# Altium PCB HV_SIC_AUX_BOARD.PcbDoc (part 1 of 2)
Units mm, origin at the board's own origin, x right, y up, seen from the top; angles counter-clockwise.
Board outline 121.92 x 53.34 mm, 4 copper layers (TOP, GND02, PWR03, BOTTOM), stack 1.6 mm thick; 125 components, 51 nets, 259 pads, 380 vias.
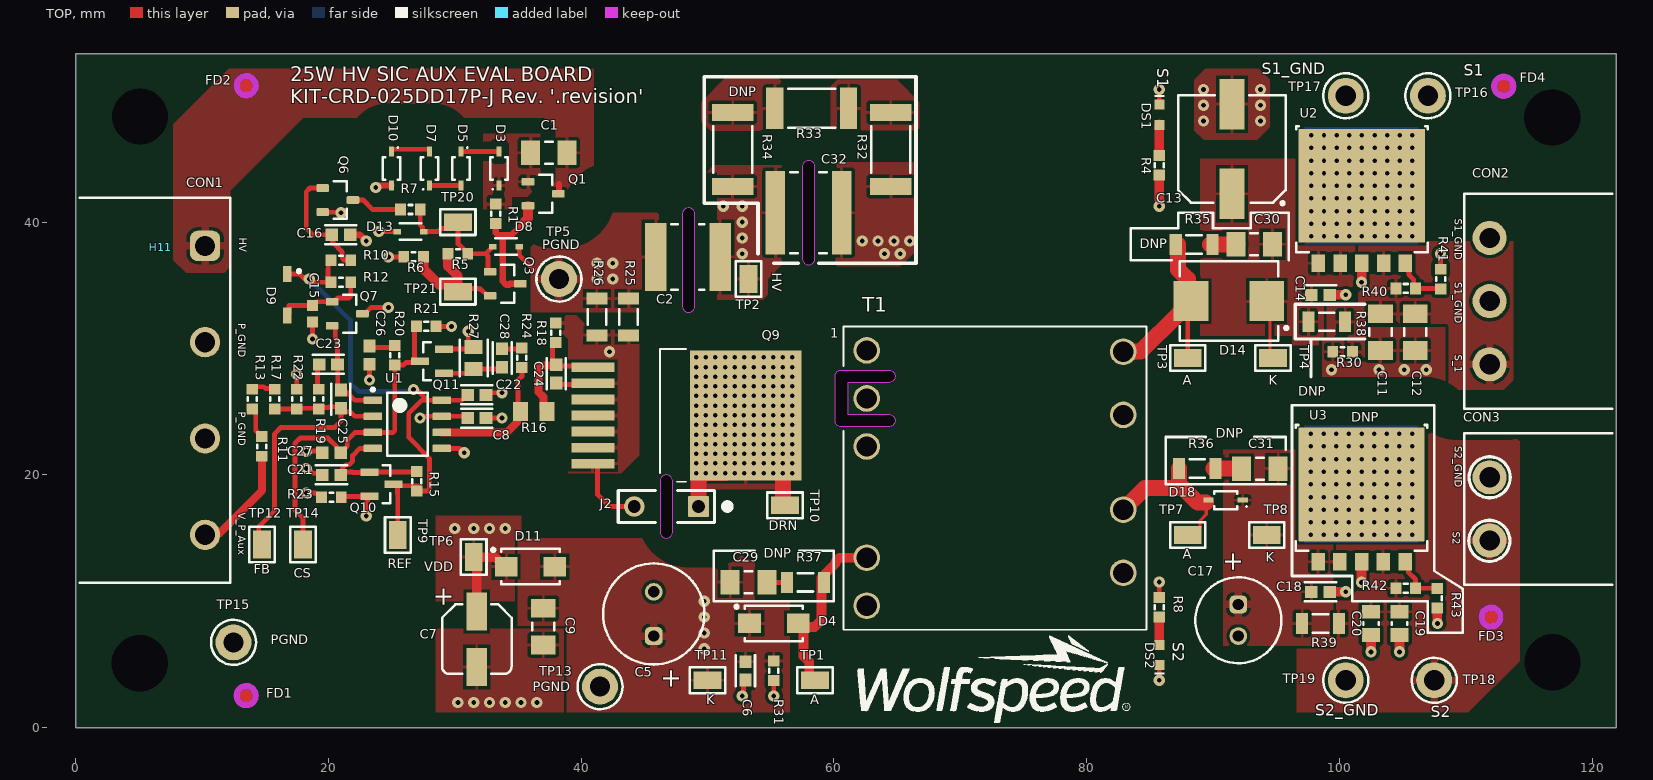
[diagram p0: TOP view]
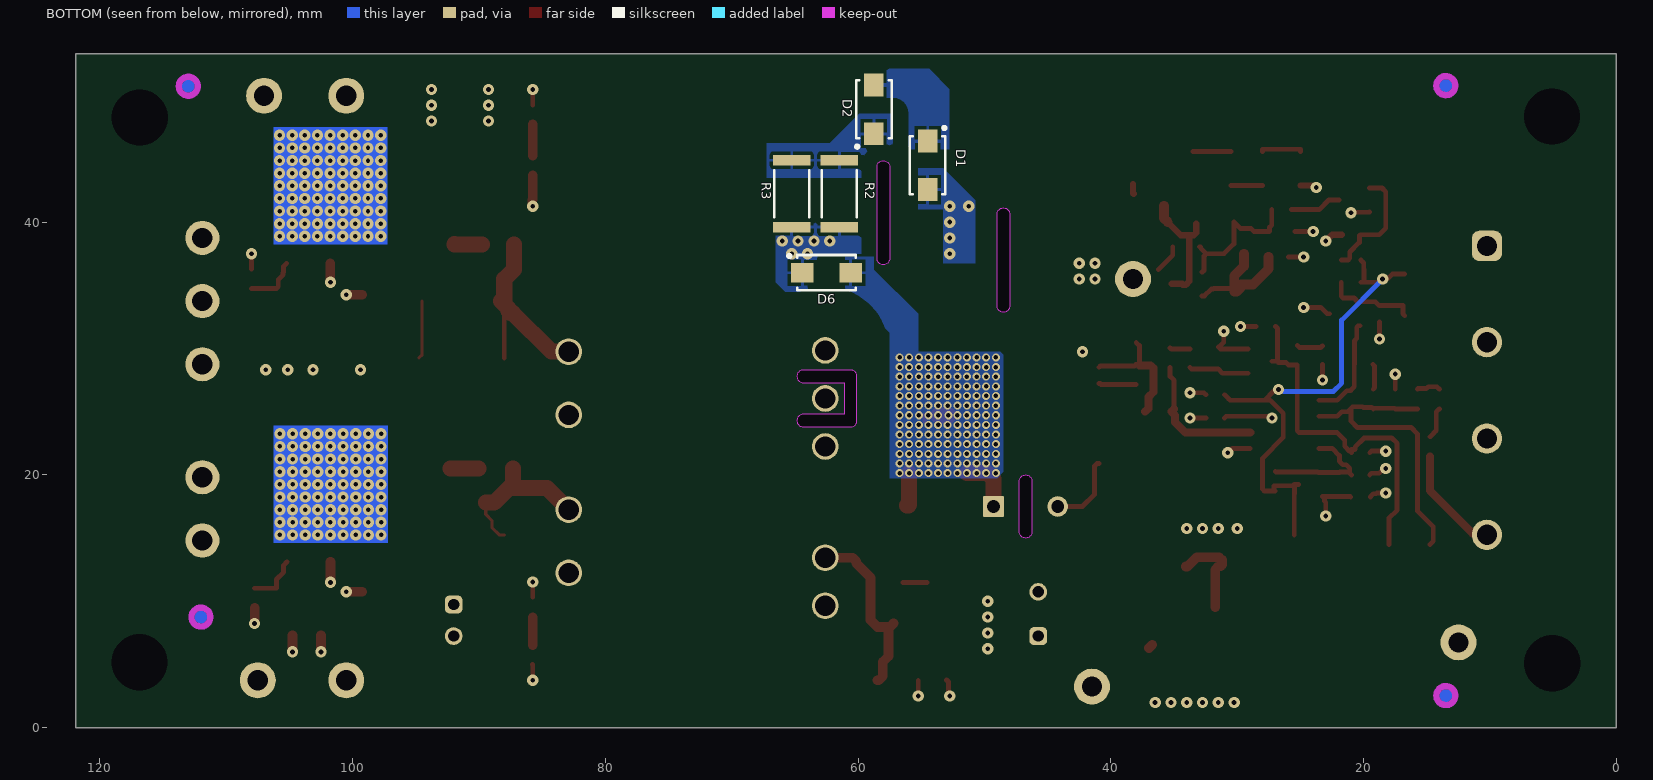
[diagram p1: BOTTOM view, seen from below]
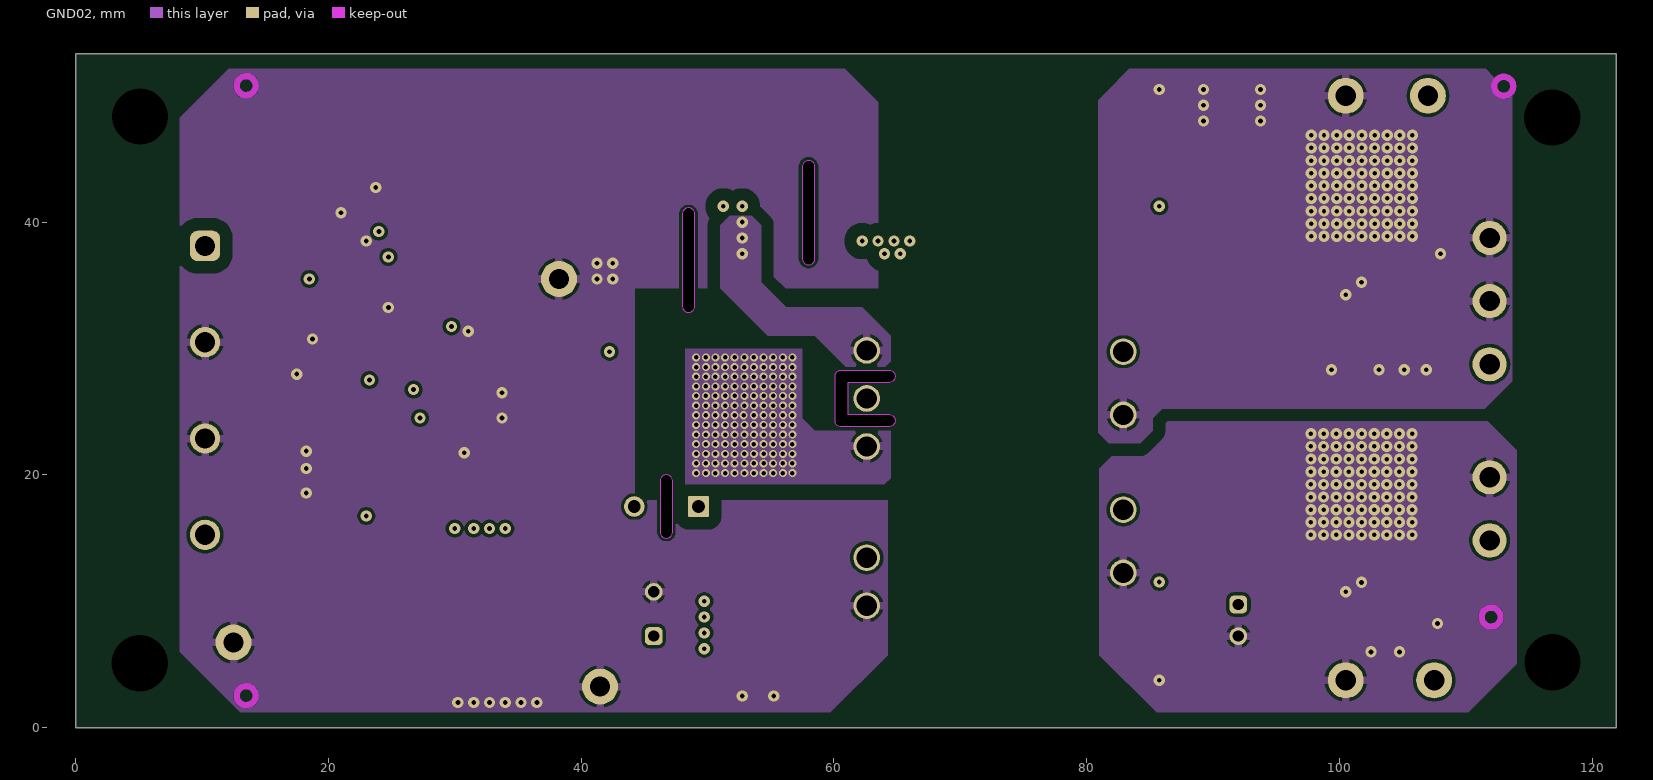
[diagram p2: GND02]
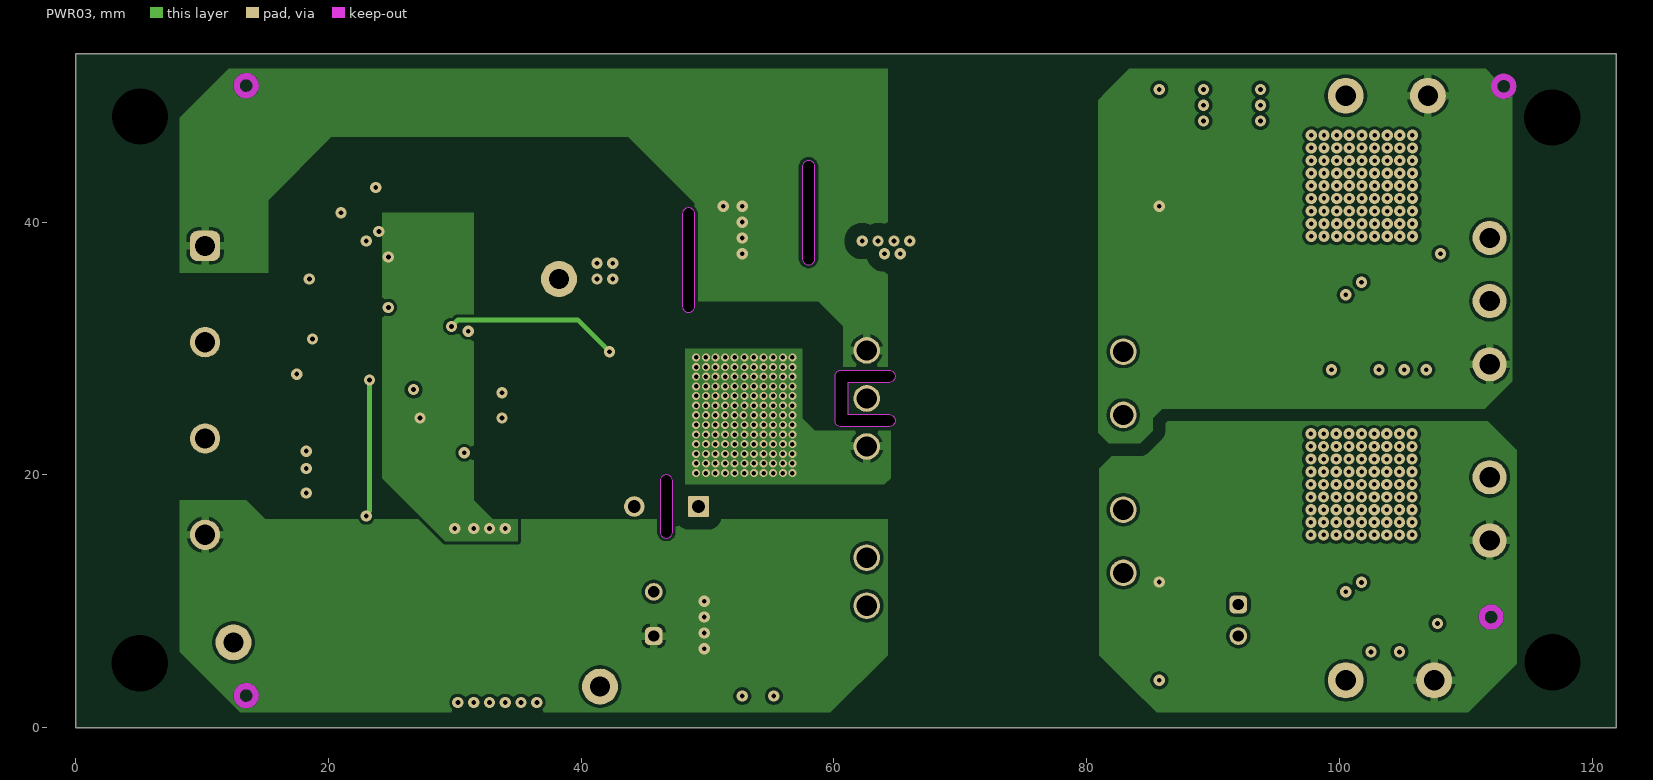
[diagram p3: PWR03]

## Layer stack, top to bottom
Top Solder: solder mask 0.0102, Solder Resist, Dk 3.5
TOP: signal copper 0.0356
Dielectric 1: prepreg 0.2159, FR-4, Dk 4.5
GND02: signal copper 0.0305
Dielectric2: core 1.0363, FR-4, Dk 4.5
PWR03: signal copper 0.0305
Dielectric3: prepreg 0.2159, FR-4, Dk 4.5
BOTTOM: signal copper 0.0356
Bottom Solder: solder mask 0.0102, Solder Resist, Dk 3.5

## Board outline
0,0 0,53.34 121.92,53.34 121.92,0
cut-out: 46.249,15.5 ccw(c46.75,15.5) 47.25,15.5 47.25,19.5 ccw(c46.75,19.5) 46.249,19.5
cut-out: 57.499,37.125 ccw(c58,37.125) 58.5,37.125 58.5,44.375 ccw(c58,44.375) 57.499,44.375
cut-out: 48,33.375 ccw(c48.5,33.375) 49.001,33.375 49.001,40.625 ccw(c48.5,40.625) 48,40.625

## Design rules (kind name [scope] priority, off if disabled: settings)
BoardOutlineClearance "BoardOutlineClearance Outer" [All] p1: gap=0.254 ignorepadtopadclearanceinfootprint=FALSE except(0: Arc-SplitContinuation Track-SplitContinuation SMDPad-SplitContinuation THPad-SplitContinuation Via-SplitContinuation Fill-SplitContinuation Poly-SplitContinuation Region-SplitContinuation Text-SplitContinuation; 1.2: Poly-OutlineEdge)
Clearance "Clearance Keepout" [IsKeepOut] p1: gap=0 ignorepadtopadclearanceinfootprint=FALSE
Clearance HV_INT [InNetClass('HV') and OnMid vs InNetClass('ISO') or InNetClass('P15') or InNetClass('Sec') or InNetClass('SW')] p2: gap=1 ignorepadtopadclearanceinfootprint=TRUE
Clearance SW_INT [InNetClass('SW')AND OnMid vs InNetClass('Sec')or InNetClass('ISO')or InNetClass('HV')  or InNetClass('P15')] p3: gap=1 ignorepadtopadclearanceinfootprint=FALSE
Clearance P15_INT [InNetClass('P15')AND OnMid vs InNetClass('Sec')or InNetClass('ISO')or InNetClass('HV')  or InNetClass('SW')] p4: gap=1 ignorepadtopadclearanceinfootprint=FALSE
Clearance SEC_INT [InNetClass('Sec')AND OnMid vs InNetClass('HV') or InNetClass('ISO') or InNetClass('P15') or InNetClass('SW')] p5: gap=1 ignorepadtopadclearanceinfootprint=FALSE
Clearance ISO_INT [InNetClass('ISO') and OnMid vs InNetClass('HV') or InNetClass('P15') or InNetClass('Sec') or InNetClass('SW')] p6: gap=1 ignorepadtopadclearanceinfootprint=FALSE
Clearance HV_EXT [InNetClass('HV') and (OnOutside or OnMultiLayer) vs InNetClass('ISO') or InNetClass('P15') or InNetClass('Sec') or InNetClass('SW')] p7: gap=4.01 ignorepadtopadclearanceinfootprint=FALSE
Clearance SW_EXT [InNetClass('SW')AND (OnOutside or OnMultiLayer) vs InNetClass('Sec')or InNetClass('ISO')or InNetClass('HV') or InNetClass('P15')] p8: gap=4.01 ignorepadtopadclearanceinfootprint=FALSE
Clearance P15_EXT [InNetClass('P15')AND (OnOutside or OnMultiLayer) vs InNetClass('Sec')or InNetClass('ISO')or InNetClass('HV') or InNetClass('SW')] p9: gap=4.01 ignorepadtopadclearanceinfootprint=FALSE
Clearance SEC_EXT [InNetClass('Sec')AND (OnOutside or OnMultiLayer) vs InNetClass('HV') or InNetClass('ISO') or InNetClass('P15')or InNetClass('SW')] p10: gap=4.01 ignorepadtopadclearanceinfootprint=FALSE
Clearance ISO_Ext [InNetClass('ISO') and (OnOutside or OnMultiLayer) vs InNetClass('HV') or InNetClass('P15') or InNetClass('Sec') or InNetClass('SW')] p11: gap=4.01 ignorepadtopadclearanceinfootprint=FALSE
Clearance "HV - ZV520 (260V)" [InNetClass('ZV520') vs InNetClass('HV')] p12: gap=1.25 ignorepadtopadclearanceinfootprint=FALSE
Clearance "HV - ZV260 (540V)" [InNetClass('V260') vs InNetClass('HV')] p13: gap=2.7 ignorepadtopadclearanceinfootprint=FALSE
Clearance "HV - ZV130 (670V)" [InNetClass('ZV130') vs InNetClass('HV')] p14: gap=3.4 ignorepadtopadclearanceinfootprint=FALSE
Clearance "ZV520 - ZV390 (130V)" [InNetClass('ZV520') vs InNetClass('ZV390')] p15: gap=0.6 ignorepadtopadclearanceinfootprint=FALSE
Clearance "ZV520 - ZV260 (260V)" [InNetClass('ZV520') vs InNetClass('ZV260')] p16: gap=1.25 ignorepadtopadclearanceinfootprint=FALSE
Clearance "ZV520 - ZV130 (390V)" [InNetClass('ZV520') vs InNetClass('ZV260')] p17: gap=2.5 ignorepadtopadclearanceinfootprint=FALSE
Clearance "ZV390 - ZV130 (260V)" [InNetClass('ZV390') vs InNetClass('ZV130')] p18: gap=1.25 ignorepadtopadclearanceinfootprint=FALSE
Clearance "ZV390 - ZV260 (130V)" [InNetClass('ZV390') vs InNetClass('ZV260')] p19: gap=0.6 ignorepadtopadclearanceinfootprint=FALSE
Clearance "ZV260 - ZV130 (130V)" [InNetClass('ZV390') vs InNetClass('ZV260')] p20: gap=0.6 ignorepadtopadclearanceinfootprint=FALSE
Clearance "Snubber Resistors" [InNetClass('V520') or InNetClass('V260')] p21: gap=2.5 ignorepadtopadclearanceinfootprint=FALSE
Clearance "TVS Diodes" [InNetClass('TVS_300V') or InNetClass('TVS_600V')] p22: gap=1.25 ignorepadtopadclearanceinfootprint=FALSE
Clearance "Clearance Default" [All] p23: gap=0.254 ignorepadtopadclearanceinfootprint=FALSE
ComponentClearance [All] p1 off: gap=0.001 collisioncheckmode=3 verticalgap=1.27 showdistances=FALSE
Creepage "Creepage HV" [InNetClass('HV') vs InNetClass('ISO') or InNetClass('P15') or InNetClass('Sec') or InNetClass('SW')] p1: checkdistance=4
Creepage "Creepage SW" [InNetClass('SW') vs InNetClass('ISO') or InNetClass('P15') or InNetClass('Sec') or InNetClass('HV')] p2: checkdistance=4
Creepage "Creepage P15" [InNetClass('P15') vs InNetClass('ISO') or InNetClass('SW') or InNetClass('Sec') or InNetClass('HV')] p3: checkdistance=4
Creepage "Creepage SEC" [InNetClass('Sec') vs InNetClass('ISO') or InNetClass('SW') or InNetClass('P15') or InNetClass('HV')] p4: checkdistance=4
Creepage "Creepage ISO" [InNetClass('ISO') vs InNetClass('Sec') or InNetClass('SW') or InNetClass('P15') or InNetClass('HV')] p5: checkdistance=4
HoleSize [All] p1: absolutevalues=TRUE maxlimit=5.08 minlimit=0.025 maxpercent=80.000 minpercent=20.000
MinimumSolderMaskSliver [All] p1: minsoldermaskwidth=0.102
PlaneConnect [All] p1: planeconnectstyle=Direct reliefexpansion=0.508 reliefentries=4 reliefconductorwidth=0.254 reliefairgap=0.254
PolygonConnect [All] p1: thpad.connectstyle=Relief thpad.reliefconductorwidth=0.635 thpad.reliefentries=4 thpad.polygonreliefangle="90 Angle" thpad.airgapwidth=0.254 smdpad.connectstyle=Relief smdpad.reliefconductorwidth=0.254 smdpad.reliefentries=4 smdpad.polygonreliefangle="90 Angle" smdpad.airgapwidth=0.254 via.connectstyle=Direct via.reliefconductorwidth=0.254 via.reliefentries=4 via.polygonreliefangle="90 Angle" via.airgapwidth=0.254
RoutingVias [All] p1: holewidth=0.711 width=1.27 viastyle="Through Hole" minholewidth=0.381 minwidth=0.889 maxholewidth=0.711 maxwidth=1.27
SilkToSilkClearance [All] p1: silktosilkclearance=0.127
SilkToSolderMaskClearance [IsPad] p1: minsilkscreentomaskgap=0.051 clearancetoexposedcopper=TRUE
SolderMaskExpansion [All] p1: expansion=0.102 istentingtop=FALSE
SupplyNets "Schematic Supply Nets_10" [InNet('S_1')] p1: voltage=0.000
SupplyNets "Schematic Supply Nets_9" [InNet('S1_GND')] p2: voltage=0.000
SupplyNets "Schematic Supply Nets_8" [InNet('S2_GND')] p3: voltage=0.000
SupplyNets "Schematic Supply Nets_7" [InNet('V_P_aux')] p4: voltage=0.000
SupplyNets "Schematic Supply Nets_6" [InNet('S_2')] p5: voltage=0.000
SupplyNets "Schematic Supply Nets" [InNet('PGND')] p6: voltage=0.000
Width [All] p1: maxlimit=1.27 minlimit=0.254 preferedwidth=0.381
24 further rules are at their usual default settings.

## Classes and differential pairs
net class ZV520: NetC1_2 NetQ1_2
net class ZV260: NetD5_2
net class TVS_600V: NetD2_1
net class TVS_300V: NetD1_1
net class V520: NetR33_1
net class V260: NetR32_1
net class ZV390: NetD3_2
net class SW: NetC32_2 NetD6_2
net class ZV130: NetD7_2
net class Sec: NetC13_1 NetC30_2 NetD14_2 NetDS1_2 NetR40_2 S1_GND S_1
net class P15: COMP CS FB NETC15_1 NETC16_2 NETC23_1 NETC24_2 NETC26_1 NETC26_2 NETC28_1 NETC28_2 NetC29_2 NetD4_2 NetD8_1 NetQ3_2 NETQ6_3 NetR11_1 NETR13_1 NETR16_1 PGND RT/CT SRC V_P_aux VDD VREF
net class ISO: NETC17_1 NetC31_2 NetD18_2 NetDS2_2 NetR42_2 S2_GND S_2
net class HV: HV_IN

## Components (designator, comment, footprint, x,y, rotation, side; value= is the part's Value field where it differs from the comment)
C1 "1206Y1K01P50DAR" CAPC3316X19N#1 37.45,45.5 r180 top value=1.5pF
C2 "C2220C164KFRLCTU" WS_C2220_B_Stacked 48.45,37.25 r180 top value=160nF
C5 "870235574001" 870235574001-Footprint-1 45.75,9 r270 top value=180µF
C6 "C1608X7R1V105K080AE" FP-C0603C-CF-IPC_B#1 53.007,4.5 r270 top value=1µF
C7 "875575659001" 875575659001-Footprint-1 31.75,7 r90 top value=22µF
C8 "C1608X7R1V105K080AE" FP-C0603C-CF-IPC_B#1 31.75,24.5 r0 top value=1µF
C9 "UMK316AB7475KL-T" CAPC3316X19N#1 37,8 r270 top value=4.7µF
C11 "CL31B106KAHNFNE" CAPC3316X19N#1 103.25,31.3 r270 top value=10µF
C12 "CL31B106KAHNFNE" CAPC3316X19N#1 106,31.3 r270 top value=10µF
C13 "EEE-FP1V221AP" FP-FPF-MFG 91.5,45.79 r270 top value=220µF
C14 "06035C105KAT2A" FP-C0603C-CF-IPC_B#2 98.5,34.25 r0 top value=1µF
C15 "CC0603KRX7R8BB334" WFP_C0603_C 18.75,32.75 r270 top value=330nF
C16 "CGA3E2X7R1H223K080AA" FP-C0603C-CF-IPC_B#1 21,39 r180 top value=22nF
C17 "870235373002" WCAP-PT5H_D6.3H11 92,8.5 r90 top value=180µF
C18 "C1608X7R1V105K080AE" FP-C0603C-CF-IPC_B#1 98.5,10.75 r0 top value=1µF
C19 "CC0805MKX7R7BB106" CAPC2012X15N 104.75,8.25 r90 top value=10µF
C20 "CC0805MKX7R7BB106" CAPC2012X15N 102.5,8.25 r90 top value=10µF
C21 "GRM1885C1H102GA01D" FP-C0603C-CF-IPC_B#1 20.25,20 r0 top value=1nF
C22 "C0603C104K5RAC7411" FP-C0603C-CF-IPC_B#1 31.75,26.338 r180 top value=100nF
C23 "CGA3E2X7R1H223K080AA" FP-C0603C-CF-IPC_B#1 20,28.75 r0 top value=22nF
C24 "GRM1885C1H102GA01D" FP-C0603C-CF-IPC_B#1 38.034,28 r90 top value=1nF
C25 "CC0603KRX7R9BB101" FP-C0603C-CF-IPC_B#1 21,26 r90 top value=100pF
C26 "GMC10X7R225K16NT" FP-C0603C-CF-IPC_B#1 23.25,29.476 r90 top value=2.2µF
C27 "CC0603KRX7R9BB101" FP-C0603C-CF-IPC_B#1 20.25,21.75 r0 top value=100pF
C28 "C0603C220K5GACTU" FP-C0603C-CF-IPC_B#1 33.75,29.25 r270 top value=22pF
C29 "GRM31B5C2J102JW01L" CAPC3316X19N#2 53.25,11.5 r0 top value=1nF
C30 "GRM31B5C2J102JW01L" CAPC3316X19N#2 93.25,38.25 r180 top value=1nF
C31 "GRM31B5C2J102JW01L" CAPC3316X19N#2 93.704,20.5 r180 top value=1nF
C32 "C2225C104KFRACTU" CAPC2225(5664)150_N 58,40.75 r0 top value=100nF
CON1 "691313410004" 691313410004 6.25,26.69 r270 top
CON2 "39522-1003" 39522-1002-Footprint-1#1 111.887,31.252 r90 top locked
CON3 "39522-1002" 39522-1002-Footprint-1#2 111.887,17.312 r90 top locked
D1 "SMAJ300CA" DO-214AC_SMA_B 54.5,44.5 r270 bottom
D2 "SMAJ300CA" DO-214AC_SMA_B 58.75,48.925 r90 bottom
D3 "UDZLVFHTE-17130" WS-SOD323F_B 33.5,44.25 r90 top
D4 "S1DHE3_A/H" DO-214AC_SMA_B 55.25,8.25 r0 top
D5 "UDZLVFHTE-17130" WS-SOD323F_B 30.5,44.25 r270 top
D6 "BYG10YHE3-A/I" DO-214AC_SMA_B 62.5,36 r180 bottom
D7 "UDZLVFHTE-17130" WS-SOD323F_B 28,44.25 r90 top
D8 "BZX384C22-E3-08" DIOD-SOD323-2-A_V 34.055,38.057 r180 top
D9 "1N5819HW-7-F" WS_SOD123_B 16.75,34.25 r270 top
D10 "UDZLVFHTE-17130" WS-SOD323F_B 25,44.25 r270 top
D11 "SS16HE3_B/H" DO-214AC_SMA_B 36,12.75 r0 top
D13 "MM3Z18VT1G" DIOD-SOD323-2-A_V 26.5,39.25 r0 top
D14 "SK815" "DO-214AB (SMC) MD" 91.25,33.75 r180 top
D18 "BAS100CS_R1_00001" WS-SOD323F_B 91,18 r180 top
DS1 "S1" WL-SMCW_0603_150060xx75000 85.75,48.5 r270 top
DS2 "S2" WL-SMCW_0603_150060xx75000 85.75,5.75 r90 top
FD1 "FID1X2R Two Sided" "FID1X2R Two Sided-Footprint-1" 13.5,2.54 r0 top
FD2 "FID1X2R Two Sided" "FID1X2R Two Sided-Footprint-1" 13.5,50.8 r0 top
FD3 "FID1X2R Two Sided" "FID1X2R Two Sided-Footprint-1" 112,8.75 r0 top
FD4 "FID1X2R Two Sided" "FID1X2R Two Sided-Footprint-1" 113,50.75 r0 top
H11 "691351400004" 691351400004 6.75,38 r270 top
J2 "TSW-202-08-G-S" TSW-202-24-T-S-Footprint-2 46.75,17.5 r180 top
Q1 "BSS126H6906XTSA1" WFP_SOT23-3_IPC_B 37,42.25 r0 top
Q3 "BSS126H6906XTSA1" WFP_SOT23-3_IPC_B 34,35.115 r0 top
Q6 "2N7002_215" WFP_SOT23-3_IPC_B 20.75,41.75 r0 top
Q7 "PMBT2907A,235" WFP_SOT23-3_IPC_B 21.5,32.75 r0 top
Q9 "C3M0900170J" TO-263-7XL_CRW 50.927,24.702 r270 top locked
Q10 "MMBT3904215" NXP-SOT23_N 24.215,19.25 r0 top
Q11 "MMBT3904215" NXP-SOT23_N 28.2,29 r180 top
R1 "RMCF0603FT1M00" FP-AC0603-IPC_B#1 33.25,40.664 r90 top value=1M
R2 "CRCW201061R9FKEFHP" R2010_MD 61.5,42.25 r90 bottom value=61.9
R3 "CRCW201061R9FKEFHP" R2010_MD 65.25,42.25 r90 bottom value=61.9
R4 "RMCF0603FT3K90" FP-AC0603-IPC_B#1 85.75,44.5 r270 top value=3.9k
R5 "RMCF0603FT1M00" FP-AC0603-IPC_B#1 30.25,37.5 r0 top value=1M
R6 "RMCF0603FG1K00" FP-AC0603-IPC_B#1 26.75,37.25 r0 top value=1k
R7 "RG1608P-103-B-T5" FP-AC0603-IPC_B#1 26.5,41 r0 top value=10k
R8 "RMCF0603FG1K00" FP-AC0603-IPC_B#1 85.75,9.527 r90 top value=1k
R10 "RG1608P-103-B-T5" FP-AC0603-IPC_B#1 21,37 r0 top value=10k
R11 "Copy of ERJ-3EKF2701V" FP-AC0603-IPC_B#1 14.75,22.25 r270 top value=2.49k
R12 "RMCF0603FT20K0" FP-AC0603-IPC_B#1 21,35.25 r180 top value=20k
R13 "Copy of ERJ-3EKF2701V" FP-AC0603-IPC_B#1 14,26 r270 top value=2.49k
R15 "AC0603FR-0740K2L" FP-AC0603-IPC_B#1 27,19.5 r90 top value=40.2k
R16 "RC0805FR-1310RL" RESC2012X05M 36.25,25 r0 top value=10
R17 "RT0603BRE0715KL" FP-AC0603-IPC_B#1 15.75,26 r270 top value=15k
R18 "RG1608P-103-B-T5" FP-AC0603-IPC_B#1 38,31.25 r90 top value=10k
R19 "AC0603FR-07324KL" FP-AC0603-IPC_B#1 19.25,26 r90 top value=324k
R20 "RMCF0603FT4K02" FP-AC0603-IPC_B#1 25.25,29.473 r270 top value=4.02k
R21 "RMCF0603FG1K00" FP-AC0603-IPC_B#1 27.75,31.75 r0 top value=1k
R22 "RMCF0603FT3K30" FP-AC0603-IPC_B#1 17.5,26 r270 top value=3.3k
R23 "RT0603BRE0715KL" FP-AC0603-IPC_B#1 20.25,18.25 r180 top value=15k
R24 "ERJ-3EKF2001V" FP-AC0603-IPC_B#1 35.313,29.277 r270 top value=2k
R25 "CRCW12061R80FKEAHP" RESC3015X06N#1 43.75,32.5 r90 top value=1.8
R26 "CRCW12061R80FKEAHP" RESC3015X06N#1 41.25,32.5 r90 top value=1.8
R27 "CRGP0805F120R" FP-CRGP0805-IPC_B 31.5,29.25 r90 top value=120
R30 "56k 0603" FP-AC0603-IPC_B#1 100.25,29.75 r0 top value=56k
R31 "56k 0603" FP-AC0603-IPC_B#1 55.25,4.5 r90 top value=56k
R32 "CRCW2512150KFKEG" RESC6332X07N 64.5,45.75 r270 top value=150k
R33 "CRCW2512150KFKEG" RESC6332X07N 58.25,49 r0 top value=150k
R34 "CRCW2512150KFKEG" RESC6332X07N 52,45.75 r90 top value=150k
R35 "CRCW1206100RFKEA" RESC3015X06N#1 88.5,38.229 r0 top value=100
R36 "CRCW1206100RFKEA" RESC3015X06N#1 88.75,20.5 r0 top value=100
R37 "CRCW1206100RFKEA" RESC3015X06N#1 57.75,11.5 r180 top value=100
R38 "RC1206JR-100RL" RESC3015X06N#2 99,32.116 r0 top value=0
R39 "RC1206JR-100RL" RESC3015X06N#2 98.5,8.25 r0 top value=0
R40 "RC0603FR-0776K8L" FP-AC0603-IPC_B#1 105.25,34.75 r0 top value=76.8k
R41 "RMCF0603FT4K02" FP-AC0603-IPC_B#1 108,35.5 r90 top value=4.02k
R42 "56k 0603" FP-AC0603-IPC_B#1 105.25,11.03 r0 top value=56k
R43 "Resistor 10k +/-1% 0603 100 mW" FP-AC0603-IPC_B#2 107.75,10.25 r270 top value=10k
T1 "750345357" 750345357-Footprint-1 72.75,19.75 r0 top
TP1 "A" TEST_POINT_SM_REC 58.5,3.75 r90 top
TP2 "HV" TEST_POINT_SM_REC 53.25,35.5 r0 top
TP3 "A" TEST_POINT_SM_REC 88,29.25 r90 top
TP4 "K" TEST_POINT_SM_REC 94.75,29.25 r90 top
TP5 "PGND" 5012-Footprint-1 38.25,35.5 r90 top
TP6 "VDD" TEST_POINT_SM_REC 31.5,13.5 r180 top
TP7 "A" TEST_POINT_SM_REC 88,15.25 r270 top
TP8 "K" TEST_POINT_SM_REC 94.25,15.25 r270 top
TP9 "REF" TEST_POINT_SM_REC 25.5,15.25 r180 top
TP10 "DRN" TEST_POINT_SM_REC 56.134,17.59 r90 top
TP11 "K" TEST_POINT_SM_REC 50,3.75 r90 top
TP12 "FB" TEST_POINT_SM_REC 14.75,14.5 r180 top
TP13 "PGND" 5012-Footprint-1 41.5,3.25 r90 top
TP14 "CS" TEST_POINT_SM_REC 18,14.5 r0 top
TP15 "PGND" 5012-Footprint-1 12.5,6.75 r90 top
TP16 "S1" 5012-Footprint-1 107,50 r90 top
TP17 "S1_GND" 5012-Footprint-1 100.5,50 r90 top
TP18 "S2" 5012-Footprint-1 107.5,3.75 r90 top
TP19 "S2_GND" 5012-Footprint-1 100.5,3.75 r90 top
TP20 "Q3_G" TEST_POINT_SM_REC 30.25,40 r270 top
TP21 "Q3_SRC" TEST_POINT_SM_REC 30.25,34.5 r90 top
U1 "UCC28C58QDRQ1" WFP_SOIC127P6-8_IPC-B 26.25,24 r0 top
U2 "BD00FD0WHFP-TR" BD00FD0WHFP-TR-Footprint-1 101.78,42.875 r0 top
U3 "BD00FD0WHFP-TR" BD00FD0WHFP-TR-Footprint-1 101.75,19.25 r0 top

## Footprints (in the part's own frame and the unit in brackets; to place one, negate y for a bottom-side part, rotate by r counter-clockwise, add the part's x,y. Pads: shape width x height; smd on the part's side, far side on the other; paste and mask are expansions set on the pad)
5012-Footprint-1 [mil]
  round 112 hole 63: 1(0,0)
  silkscreen extent -70,-70 70,70, body extent -63,-63 63,63, height 320
39522-1002-Footprint-1#1 [mm]
  round 2.7 hole 1.6: 1(-2.5,0) 2(2.5,0) 3(7.5,0)
  silkscreen extent -6,-9.68 11,2, body extent -6,-9.94 11,2, height 8.38
39522-1002-Footprint-1#2 [mm]
  round 2.7 hole 1.6: 1(-2.5,0) 2(2.5,0)
  silkscreen extent -6,-9.68 6,2, body extent -5.99,-10 5.99,1.94, height 8.38
750345357-Footprint-1 [mil]
  round 83 hole 63: 1(-399.61,397.64) 2(-399.61,248.03) 3(-399.61,98.42) 5(-399.61,-248.03) 6(-399.61,-397.64) 8(399.61,-295.28) 10(399.61,-98.43) 12(399.61,196.85) 14(399.61,393.7)
  Keep-Out Layer board cut-out: -458.66,297.24 -458.66,198.82 -330.71,198.82 -322.21,196.88 -315.39,191.44 -311.6,183.58 -311.6,174.86 -315.39,167 -322.21,161.57 -330.71,159.63 -330.71,159.63 -478.21,159.33 -485.79,160.82 -492.22,165.11 -496.52,171.53 -498.03,179.11 -498.03,179.11 -498.03,316.93 -496.53,324.46 -492.27,330.85 -485.88,335.12 -478.35,336.61 -478.35,336.61 -330.71,336.61 -322.17,334.66 -315.32,329.2 -311.52,321.31 -311.52,312.55 -315.32,304.66 -322.17,299.19 -330.71,297.24 -330.71,297.24
  silkscreen extent -472,-472 472,472
691313410004 [mm] "7.62 mm - Closed Horizonal PCB Header - 4p"
  rrect50% 2.4x2.4 hole 1.6: 1(-11.43,4)
  round 2.4 hole 1.6: 2(-3.81,4) 3(3.81,4) 4(11.43,4)
  silkscreen extent -15.23,-5.9 15.23,6, body extent -15.24,-6 15.24,6, height 8.55
691351400004 [mm]
  body extent -2.81,-16.77 25.67,1.5, height 15.12
870235574001-Footprint-1 [mm]
  rrect50% 1.4x1.4 hole 0.9: 1(1.75,0)
  round 1.4 hole 0.9: 2(-1.75,0)
  silkscreen extent -4,-4 4,4, body extent -4.05,-4.03 3.95,3.97, height 11.5
875575659001-Footprint-1 [mm]
  rect 3x1.6 smd: 1(2.2,0) 2(-2.2,0)
  silkscreen extent -2.75,-2.75 2.75,2.75, body extent -2.95,-2.65 2.95,2.65, height 5.85
BD00FD0WHFP-TR-Footprint-1 [mm]
  rrect1% 1.07x1.37 smd paste-0.05: 1(-3.44,-6.125) 2(-1.72,-6.125) 3(0,-6.125) 4(1.72,-6.125) 5(3.44,-6.125)
  rrect1% 10x9 smd paste-0.05: 6(0,0)
  silkscreen extent -5.2,-5.26 5.2,4.7, body extent -4.7,-6.29 4.7,4.25, height 1.91
CAPC2012X15N [mm] "Chip Capacitor, 2-Leads, Body 2.00x1.25mm, IPC Medium Density"
  rrect1% 1.1x1.45 smd: 1(-0.925,0) 2(0.925,0)
  silkscreen extent -0.1,-0.63 0.1,0.63, body extent -1.1,-0.72 1.1,0.72, height 1.1
CAPC2225(5664)150_N [mm] "Chip Capacitor, Body 5.7x6.4mm, Height 1.5mm, IPC Medium Density"
  rrect1% 1.55x6.6 smd: 1(-2.625,0) 2(2.625,0)
  silkscreen extent -1.45,-3.2 1.45,3.2, body extent -3,-3.4 3,3.4, height 1.5
CAPC3316X19N#1 [mm] "Chip Capacitor, 2-Leads, Body 3.30x1.60mm, IPC Medium Density"
  rrect1% 1.5x1.95 smd: 1(-1.45,0) 2(1.45,0)
  silkscreen extent -0.3,-0.87 0.3,0.87, body extent -1.85,-0.98 1.85,0.97, height 1.9
CAPC3316X19N#2 [mm] "Chip Capacitor, 2-Leads, Body 3.30x1.60mm, IPC Medium Density"
  rect 1.5x1.95 smd: 1(-1.45,0) 2(1.45,0)
  silkscreen extent -0.3,-0.87 0.3,0.87, body extent -1.85,-0.98 1.85,0.97, height 1.9
DIOD-SOD323-2-A_V [mm] "SOD-323, 2-Leads, Body 1.7x1.3mm, Lead Span 2.5mm"
  rect 0.59x0.45 smd: 1(1.055,0) 2(-1.055,0)
  silkscreen extent -0.85,-0.65 0.85,0.65, body extent -1.24,-0.7 1.24,0.7, height 1.2
"DO-214AB (SMC) MD" [mm] "Molded Diode, 2-Leads, Body 7.18x5.91mm, IPC Medium Density"
  rect 2.75x3.15 smd: 1(-3,0) 2(3,0)
  silkscreen extent -4.67,-3.15 3.9,3.15, body extent -4.1,-3.11 4.1,3.11, height 2.63
DO-214AC_SMA_B [mm] "Molded Diode, 2-Leads, Body 4.25x2.59mm, IPC Medium Density"
  rect 1.8x1.55 smd: 1(-1.925,0) 2(1.925,0)
  silkscreen extent -3.07,-1.4 2.3,1.45, body extent -2.3,-1.4 2.3,1.39, height 2.29
"FID1X2R Two Sided-Footprint-1" [mm]
  TOP circle w0.5: c0,0 r0.25
  BOTTOM circle w0.5: c0,0 r0.25
  Keep-Out Layer circle w0.5: c0,0 r0.75
FP-AC0603-IPC_B#1 [mm]
  rrect1% 0.859x0.912 smd paste+0: 1(-0.777,0) 2(0.777,0)
  silkscreen extent -0.15,-0.36 0.15,0.36, body extent -0.8,-0.45 0.8,0.45, height 0.5
FP-AC0603-IPC_B#2 [mm]
  rrect1% 0.859x0.912 smd paste+0 mask+0: 1(-0.777,0) 2(0.777,0)
  silkscreen extent -0.15,0.36 0.15,0.36, body extent -0.8,-0.45 0.8,0.45, height 0.5
FP-C0603C-CF-IPC_B#1 [mm]
  rect 1.007x0.958 smd paste+0 mask+0: 1(-0.726,0) 2(0.726,0)
  silkscreen extent -1.23,-0.75 1.23,0.75, body extent -0.8,-0.4 0.8,0.4, height 0.89
FP-C0603C-CF-IPC_B#2 [mm]
  rrect1% 1.007x0.958 smd paste+0: 1(-0.726,0) 2(0.726,0)
  silkscreen extent -1.23,-0.75 1.23,0.75, body extent -0.8,-0.4 0.8,0.4, height 0.89
FP-CRGP0805-IPC_B [mm]
  rrect1% 1.106x1.41 smd paste+0: 1(-0.876,0) 2(0.876,0)
  silkscreen extent -1.43,-1.1 1.43,1.1, body extent -1.68,-0.95 1.68,0.95, height 0.25
FP-FPF-MFG [mm]
  rect 4x2 smd paste+0 mask+0: 1(3.55,0) 2(-3.55,0)
  silkscreen extent -4.25,-4.25 4.41,4.25, body extent -4.95,-4.15 4.95,4.15, height 10.51
NXP-SOT23_N [mm] "SOT23, 3-Leads, Body 3x1.4mm, Pitch 0.95mm, IPC Medium Density"
  rrect1% 1.4x0.6 smd: 1(-0.95,0.95) 2(-0.95,-0.95) 3(0.95,0)
  silkscreen extent 0.1,-1.5 0.7,1.5, body extent -1.3,-1.5 1.3,1.5, height 1.1
R2010_MD [mm] "2010 Chip resistor Class B - Medium density"
  rrect1% 0.85x2.95 smd: 1(-2.65,0) 2(2.65,0)
  silkscreen extent -1.85,-1.37 1.85,1.38, body extent -2.42,-1.17 2.42,1.18, height 0.71
RESC2012X05M [mm] "Chip Resistor, 2-Leads, Body 2.05x1.25mm, IPC Low Density"
  rrect1% 1.2x1.5 smd: 1(-1.05,0) 2(1.05,0)
  body extent -1.1,-0.7 1.1,0.7, height 0.5
RESC3015X06N#1 [mm] "Chip Resistor, 2-Leads, Body 3.05x1.55mm, IPC Medium Density"
  rect 0.95x1.65 smd: 1(-1.45,0) 2(1.45,0)
  silkscreen extent -0.6,-0.72 0.6,0.72, body extent -1.6,-0.82 1.6,0.82, height 0.71
RESC3015X06N#2 [mm] "Chip Resistor, 2-Leads, Body 3.05x1.55mm, IPC Medium Density"
  rrect1% 0.95x1.65 smd: 1(-1.45,0) 2(1.45,0)
  silkscreen extent -0.6,-0.72 0.6,0.72, body extent -1.6,-0.82 1.6,0.82, height 0.71
RESC6332X07N [mm] "Chip Resistor, 2-Leads, Body 6.30x3.15mm, IPC Medium Density"
  rrect1% 1.35x3.3 smd: 1(-2.925,0) 2(2.925,0)
  silkscreen extent -1.85,-1.55 1.85,1.55, body extent -3.25,-1.65 3.25,1.65, height 0.7
TEST_POINT_SM_REC [mil] "TEST_POINT_SM_REC"
  rrect1% 55x87 smd: 1(0,0)
  silkscreen extent -40,-55 40,55, body extent -24,-39 24,39, height 55
TO-263-7XL_CRW [mil]
  rect 30x134 smd paste+0 mask+0: 1(-150,-393.5) 2(-100,-393.5) 3(-50,-393.5) 4(0,-393.5) 5(50,-393.5) 6(100,-393.5) 7(150,-393.5)
  rect 405x348 smd paste+0 mask+0: 8(0,82.5)
  silkscreen extent -206,-185 207,-104, body extent -200,-402 200,234, height 175
TSW-202-24-T-S-Footprint-2 [mil]
  rrect1% 64x64 hole 40: 1(-100,0)
  round 64 hole 40: 2(100,0)
  silkscreen extent -200,-50 150,50, body extent -150,-50 150,50, height 282
WCAP-PT5H_D6.3H11 [mm] "Aluminum Polymer Capacitors, body Diameter 6.3mm"
  rrect50% 1.4x1.4 hole 0.9: 1(1.25,0)
  round 1.4 hole 0.9: 2(-1.25,0)
  silkscreen extent -3.4,-3.4 3.4,3.4, body extent -3.14,-3.15 3.12,3.13, height 11.31
WFP_C0603_C [mm] "C0603 Level C - high density"
  rrect1% 0.85x0.9 smd: 1(-0.65,0) 2(0.65,0)
  body extent -0.88,-0.48 0.87,0.48, height 0.85
WFP_SOIC127P6-8_IPC-B [mm] "SOIC, 8-Leads, Pitch 1.27mm, 6mm Lead Span, Body 5x4mm, IPC Medium Density (N/B)"
  rrect17% 1.45x0.6 smd: 1(-2.725,1.905) 2(-2.725,0.635) 3(-2.725,-0.635) 4(-2.725,-1.905) 5(2.725,-1.905) 6(2.725,-0.635) 7(2.725,0.635) 8(2.725,1.905)
  silkscreen extent -2.85,-2.5 1.6,2.88, body extent -3,-2.5 3,2.5, height 1.75
WFP_SOT23-3_IPC_B [mm] "SOT23, 3 lead, IPC Medium Density"
  rrect25% 1x0.6 smd: 1(-1.2,0.95) 2(-1.2,-0.95) 3(1.2,0)
  silkscreen extent -0.3,-1.5 0.7,1.5, body extent -1.3,-1.5 1.3,1.5, height 1.1
WL-SMCW_0603_150060xx75000 [mm] "SMD Mono-color Chip LED, body 1.60 x 0.80 mm"
  rect 0.8x0.8 smd: 1(-0.8,0) 2(0.8,0)
  silkscreen extent -1.55,-0.4 -1.4,0.4, body extent -0.8,-0.4 0.8,0.4, height 0.7
WS-SOD323F_B [mm] "SOD323 Level B - medium density"
  rrect1% 0.8x0.4 smd: 1(-1.35,0) 2(1.35,0)
  silkscreen extent -1.7,-0.7 0.9,0.7, body extent -1.25,-0.67 1.25,0.68, height 0.9
WS_C2220_B_Stacked [mm] "C2220 Level B - medium density"
  rect 1.7x5.4 smd: 1(-2.55,0) 2(2.55,0)
  silkscreen extent -1.3,-2.6 1.3,2.6, body extent -3.05,-2.7 3.05,2.7, height 5.6
WS_SOD123_B [mm] "SOD123 Level B - medium density"
  rrect1% 1.257x0.702 smd paste+0: 1(-1.65,0) 2(1.65,0)
  silkscreen extent -2,0.8 -1.75,1.05, body extent -1.85,-0.85 1.85,0.85, height 1.35

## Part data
C1: library part CMP-001-00194-6, "MLCC, 1206, Y5V, 1uf, .10%, 0.50Vdc, Palliadum Silver", Capacitor Type=Ceramic, Case/Package=1206, Max Operating Temperature=125°C, Min Operating Temperature=-55°C, Temperature Coefficient=COG/NPO, TOLERANCE=33%, Voltage Rating=1kV
C2: library part CMP-001-00220-1, "0.16 µF ±10% 1500V (1.5kV) Ceramic Capacitor X7R 2220", Capacitor Type=Ceramic, Case/Package="2220 Stacked", Max Operating Temperature=125°C, Min Operating Temperature=-55°C, Temperature Coefficient=X7R, TOLERANCE=10%, Voltage Rating=1.5kV
C5: library part CMP-001-00223-1, "WCAP-PT5H Aluminum Polymer Capacitors, 180uF, 16VDC, +/-20%", Capacitor Type=Electrolytic, Case/Package=Radial, Max Operating Temperature=105°C, Min Operating Temperature=-55°C, TOLERANCE=20%, Voltage Rating=16V
C6 C8 C18: library part CMP-001-00097-20, "Ceramic Capacitor, Multilayer, Ceramic, 35V, 10% +Tol, 10% -Tol, X7R, 15% TC, 1uF, Surface Mount, 0603", Capacitor Type=Ceramic, Case/Package=0603, Max Operating Temperature=125°C, Min Operating Temperature=-55°C, Temperature Coefficient=X7R, TOLERANCE=10%, Voltage Rating=35V
C7: library part CMP-001-00222-1, "WCAP-ASLL Aluminum Hybrid Electrolytic Capacitor, 22uF, 35VDC, +/-20%", Capacitor Type=Electrolytic, Case/Package="5.3W x 5.8H", Max Operating Temperature=105°C, Min Operating Temperature=-55°C, TOLERANCE=20%, Voltage Rating=35V
C9: library part CMP-001-00161-7, "Ceramic Capacitor, Multilayer, Ceramic, 4.7 µF ±10% 50V Ceramic Capacitor X7R 1206", Capacitor Type=Ceramic, Case/Package=1206, Max Operating Temperature=125°C, Min Operating Temperature=-55°C, Temperature Coefficient=X7R, TOLERANCE=10%, Voltage Rating=50V
C11 C12: library part CMP-001-00158-8, "Cap Ceramic 10uF 25V X7R 10% SMD 1206 125°C Embossed T/R", Capacitor Type=Ceramic, Case/Package=1206, Max Operating Temperature=125°C, Min Operating Temperature=-55°C, Temperature Coefficient=X7R, TOLERANCE=10%, Voltage Rating=25V
C13: library part CMP-001-00219-2, "Aluminum Electrolytic Capacitor, Polarized, Aluminum (wet), 35V, 20% +Tol, 20% -Tol, 220uF, Surface Mount, 3333", Capacitor Type=Aluminium, Case/Package=3333, Max Operating Temperature=105°C, Min Operating Temperature=-55°C, TOLERANCE=20%, Voltage Rating=35V
C14: library part CMP-001-00122-18, "Ceramic Capacitor, Multilayer, Ceramic, 50V, 10% +Tol, 10% -Tol, X7R, 15% TC, 1uF, Surface Mount, 0603", Capacitor Type=Ceramic, Case/Package=0603, Max Operating Temperature=125°C, Min Operating Temperature=-55°C, Temperature Coefficient=X7R, TOLERANCE=10%, Voltage Rating=50V
C15: library part CMP-001-00201-6, "Ceramic Capacitor, Multilayer, Ceramic, 25V, 10% +Tol, 10% -Tol, X7R, 15% TC, 0.33uF, Surface Mount, 0603", Capacitor Type=Ceramic, Case/Package=0603, Max Operating Temperature=125°C, Min Operating Temperature=-55°C, Temperature Coefficient=X7R, TOLERANCE=10%, Voltage Rating=25V
C16 C23: library part CMP-001-00120-19, "Ceramic Capacitor, Multilayer, Ceramic, 50V, 10% +Tol, 10% -Tol, X7R, 15% TC, 0.022uF, Surface Mount, 0603", Capacitor Type=Ceramic, Case/Package=0603, Max Operating Temperature=125°C, Min Operating Temperature=-55°C, Temperature Coefficient=X7R, TOLERANCE=10%, Voltage Rating=50V
C17: library part CMP-001-00221-1, "CAP ALUM POLY 180UF 20% 16V TH", Capacitor Type=Aluminium, Case/Package=Radial, Max Operating Temperature=105°C, Min Operating Temperature=-55°C, TOLERANCE=20%, Voltage Rating=16V
C19 C20: library part CMP-001-00199-5, "Ceramic Capacitor, Multilayer, Ceramic, 16V, 20% +Tol, 20% -Tol, X7R, 15% TC, 10uF, Surface Mount, 0805", Capacitor Type=Ceramic, Case/Package=0805, Max Operating Temperature=125°C, Min Operating Temperature=-55°C, Temperature Coefficient=X7R, TOLERANCE=20%, Voltage Rating=16V
C21 C24: library part CMP-001-00098-21, "Ceramic Capacitor, Multilayer, Ceramic, 50V, 2% +Tol, 2% -Tol, C0G, -/+30ppm/Cel TC, 0.001uF, Surface Mount, 0603", Capacitor Type=Ceramic, Case/Package=0603, Max Operating Temperature=125°C, Min Operating Temperature=-55°C, Temperature Coefficient=C0G, TOLERANCE=2%, Voltage Rating=50V
C22: library part CMP-001-00086-20, "Ceramic Capacitor, Multilayer, Ceramic, 50V, 10% +Tol, 10% -Tol, X7R, 15% TC, 0.1uF, Surface Mount, 0603", Capacitor Type=Ceramic, Case/Package=0603, Max Operating Temperature=125°C, Min Operating Temperature=-55°C, Temperature Coefficient=X7R, TOLERANCE=10%, Voltage Rating=50V
C25 C27: library part CMP-001-00096-18, "Ceramic Capacitor, Multilayer, Ceramic, 50V, 10% +Tol, 10% -Tol, X7R, 15% TC, 0.0001uF, Surface Mount, 0603", Capacitor Type=Ceramic, Case/Package=0603, Max Operating Temperature=125°C, Min Operating Temperature=-55°C, Temperature Coefficient=X7R, TOLERANCE=10%, Voltage Rating=50V
C26: library part CMP-001-00123-18, "Ceramic Capacitor, Multilayer, Ceramic, 16V, 10% +Tol, 10% -Tol, X7R, 15% TC, 2.2uF, Surface Mount, 0603", Capacitor Type=Ceramic, Case/Package=0603, Max Operating Temperature=125°C, Min Operating Temperature=-55°C, Temperature Coefficient=X7R, TOLERANCE=10%, Voltage Rating=16V
C28: library part CMP-001-00112-18, "Ceramic Capacitor, Multilayer, Ceramic, 50V, 1% +Tol, 1% -Tol, C0G, 30ppm/Cel TC, 0.000022uF, Surface Mount, 0603", Capacitor Type=Ceramic, Case/Package=0603, Max Operating Temperature=125°C, Min Operating Temperature=-55°C, Temperature Coefficient=C0G, TOLERANCE=1%, Voltage Rating=50V
C29 C30 C31: library part CMP-001-00217-1, "Ceramic Capacitor, Multilayer, Ceramic, 630V, 5% +Tol, 5% -Tol, C0G, 30ppm/Cel TC, 0.001uF, Surface Mount, 1206", Capacitor Type=Ceramic, Case/Package=1206, Max Operating Temperature=125°C, Min Operating Temperature=-55°C, Temperature Coefficient=COG, TOLERANCE=5%, Voltage Rating=630V
C32: library part CMP-001-00008-7, "Cap Ceramic 0.1uF 1500V X7R 10% SMD 2225 125°C Embossed Plastic T/R", Capacitor Type=Ceramic, Case/Package=2225, Max Operating Temperature=125°C, Min Operating Temperature=-55°C, TOLERANCE=10%, Voltage Rating=1.5kV
CON1: library part CMP-002-00276-1, "Strip Terminal Block, 20A, 1 Row(s), 1 Deck(s)", Max Operating Temperature=105°C, Min Operating Temperature=-40°C, Rated Current=20A, Rated Voltage=300V
CON2: library part CMP-002-00195-6, "Conn Shrouded Header (4 Sides) HDR 3 POS 5mm Solder RA Thru-Hole Eurostyle™", Case/Package="Pluggable, Shrouded Receptacle, Male Pins", Max Operating Temperature=105°C, Min Operating Temperature=-40°C
CON3: library part CMP-002-00120-6, "Conn Shrouded Header (4 Sides) HDR 2 POS 5mm Solder RA Thru-Hole Eurostyle™", Case/Package="Pluggable, Shrouded Receptacle, Male Pins", Max Operating Temperature=105°C, Min Operating Temperature=-40°C
D1 D2: library part CMP-004-00083-2, "Trans Voltage Suppressor Diode, 600W, 300V V(RWM), Bidirectional, 1 Element, Silicon, DO-214AC", Max Operating Temperature=150°C, Min Operating Temperature=-65°C
D3 D5 D7 D10: library part CMP-004-00084-2, "Zener Diode, 130V, 0.2W, Sod-323Fl Rohs Compliant: Yes", Case/Package=SOD323F, Max Operating Temperature=150, Min Operating Temperature=-55, Zener Voltage=130
D4: library part CMP-004-00089-3, "Rectifier Diode, 1 Phase, 1 Element, 1A, 400V V(RRM), Silicon, DO-214AC", Case/Package=DO-214AC, Forward Current=1A, Forward Voltage=1.1V, Max Operating Temperature=150°C, Max Surge Current=40A, Min Operating Temperature=-55°C, Peak Inverse Voltage=200V
D6: library part CMP-004-00085-3, "Standard Avalanche Rectifier 1600V 1.5A Automotive 2-Pin DO-214AC T/R", Case/Package="SMA DO-214AC", Forward Current=1.5A, Forward Voltage=1.15V, Max Operating Temperature=150°C, Max Surge Current=30A, Min Operating Temperature=-55°C, Peak Inverse Voltage=1.6kV
D8: library part CMP-004-00086-2, "Zener Diode, 22V V(Z), 5%, 0.2W, Silicon, Unidirectional", Case/Package=SOD323, Max Operating Temperature=150°C, Min Operating Temperature=-55°C, Zener Voltage=22V
D9: library part CMP-004-00065-4, "DIODE SCHOTTKY 40V 1A SOD123", Case/Package=SOD123, Forward Current=1A, Forward Voltage=450mV, Max Operating Temperature=125°C, Min Operating Temperature=-65°C
D11: library part CMP-00035-3, "Rectifier Diode, Schottky, 1 Phase, 1 Element, 1A, 60V V(RRM), Silicon, DO-214AC", Case/Package="DO-214AC SMA", Forward Current=1A, Forward Voltage=750mV, Max Operating Temperature=150°C, Max Surge Current=40A, Min Operating Temperature=-65°C, Peak Inverse Voltage=60V
D13: library part CMP-00028-3, "Vz=18V 16.8V~19.1V Izt=5mA", Case/Package=SOD-323-2, Forward Voltage=900mV, Max Operating Temperature=150°C, Max Power Dissipation=300mW, Max Reverse Current=50nA, Min Operating Temperature=-65°C, Package Quantity=1, Power Dissipation=200mW, Test Current=5mA, TOLERANCE=6%, Voltage Rating (DC)=18V, Zener Current=10mA
D14: library part CMP-00045-2, "Rectifier Diode Schottky 150V 8A 2-Pin SMC T/R", Case/Package="DO-214AB / SMC", Forward Current=8A, Forward Voltage=870mV, Max Operating Temperature=150°C, Min Operating Temperature=-50°C, Peak Inverse Voltage=150V
D18: library part CMP-00037-1, "OEMs, CMs ONLY (NO BROKERS)", Case/Package=SOD-323, Forward Voltage=850mV, Max Operating Temperature=150°C, Max Surge Current=5.5A, Min Operating Temperature=-55°C, Peak Inverse Voltage=100V
DS1 DS2: library part CMP-007-00045-2, "Single Color LED, Bright Green, Water Clear, 1.1mm", Case/Package=0603, Colour=GREEN, Forward Voltage=2V, Max Operating Temperature=85°C, Max Power Dissipation=72mW, Min Operating Temperature=-40°C
FD1 FD2 FD3 FD4: library part CMP-00028-00054-3, "Fiducial - Round 1x2mm"
H11: library part CMP-00028-00078-1, "Barrier Strip Terminal Block, 20A, 3mm2, 1 Row(s), 1 Deck(s)", Current Rating=12A, Max Operating Temperature=105°C, Min Operating Temperature=-40°C, Voltage Rating=400V
J2: library part CMP-002-00256-2, "Board Connector, 2 Contact(s), 1 Row(s), Male, Straight, 0.2 inch Pitch, Solder Terminal, Black Insulator, Receptacle", Case/Package="Pin Header, Male", Max Operating Temperature=125°C, Min Operating Temperature=-55°C
Q1 Q3: library part CMP-013-00102-1, "Trans MOSFET N-CH 600V 0.021A Automotive 3-Pin SOT-23 T/R", Case/Package=SOT23, Max Operating Temperature=150°C, Min Operating Temperature=-55°C, POWER=500mW
Q6: library part CMP-013-00011-7, "N-channel Trench MOSFET, 60 V, 300 mA, -65 to 150 degC, 3-Pin SOT-23 (TO-236AB), RoHS, Tape and Reel", Case/Package=TO-236-3, Input Capacitance=50pF, Manufacturer="NXP Semiconductors", Max Dual Supply Voltage=60V, Max Operating Temperature=150°C, Min Operating Temperature=-65°C, Package Description="3-Pin Small Outline Transistor, Body 1.3 x 2.9 mm, Pitch 0.95 mm", Package Quantity=1, Package Reference=SOT23-3, Package Version=Feb-16, POWER=830mW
